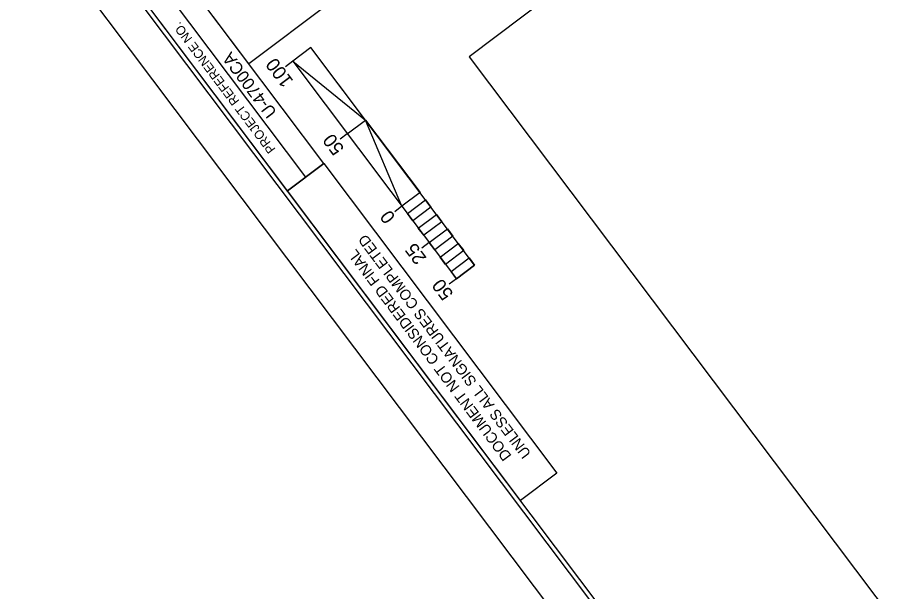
# Model space of a CAD drawing. Extents: x 1262861 to 1264804, y 775326 to 777329.
# Drawn here: x 1262916.5 to 1263399.5, y 776290.5 to 776605.9 of the extents above; entities that cross this region are included whole.
import ezdxf

# ---------------------------------------------------------------- set-up
doc = ezdxf.new("R2010")
doc.units = 0
for name, color, linetype in [('Sheet Data Field CELL', 7, 'Continuous'), ('Sheet Plan CELL', 7, 'Continuous'), ('Sheet Plot Border Inside CELL', 7, 'Continuous'), ('Sheet Plot Border Outside CELL', 7, 'Continuous'), ('Sheet Sticker Exception Certification CELL', 7, 'Continuous'), ('Sheet Title CELL', 7, 'Continuous'), ('Sheet Typical CELL', 7, 'Continuous')]:
    doc.layers.add(name, color=color, linetype=linetype)

msp = doc.modelspace()

# ---------------------------------------------------------------- linework, layer by layer
at = {"layer": 'Sheet Data Field CELL'}
for p, q in [((1263067.87, 776581.93), (1263063.88, 776578.92)), ((1263097.9, 776542.05), (1263093.92, 776539.06)), ((1263142.96, 776482.25), (1263138.97, 776479.24)), ((1263157.97, 776462.3), (1263153.99, 776459.3))]:
    msp.add_line(p, q, dxfattribs=at)
at = {"layer": 'Sheet Plan CELL'}
msp.add_lwpolyline([(1263054.56, 776753.11), (1263133.61, 776648.16), (1263043.77, 776580.5), (1262964.72, 776685.44)], dxfattribs=at)
msp.add_lwpolyline([(1263054.56, 776753.11), (1263133.61, 776648.16), (1263043.77, 776580.5), (1262964.72, 776685.44)], dxfattribs=at)
at = {"layer": 'Sheet Plot Border Inside CELL'}
msp.add_lwpolyline([(1264780.22, 775982.89), (1263777.88, 777313.61), (1262935.19, 776678.9), (1263937.52, 775348.16)], close=True, dxfattribs=at)
at = {"layer": 'Sheet Plot Border Outside CELL'}
msp.add_lwpolyline([(1262916.5, 776670.46), (1263929.36, 775325.74), (1264804.01, 775984.53), (1263791.15, 777329.26)], close=True, dxfattribs=at)
at = {"layer": 'Sheet Sticker Exception Certification CELL'}
for p, q in [((1263065.04, 776510.63), (1263085.04, 776525.69)), ((1263085.03, 776525.68), (1263213.21, 776355.5)), ((1263193.22, 776340.44), (1263065.03, 776510.62)), ((1263213.21, 776355.5), (1263193.22, 776340.44))]:
    msp.add_line(p, q, dxfattribs=at)
at = {"layer": 'Sheet Title CELL'}
for p, q in [((1263077.86, 776589.44), (1263067.88, 776581.93)), ((1263167.95, 776469.81), (1263077.86, 776589.44)), ((1263067.88, 776581.93), (1263063.89, 776578.92)), ((1263067.88, 776581.93), (1263157.99, 776462.3)), ((1263097.92, 776542.05), (1263107.88, 776549.56)), ((1263097.92, 776542.05), (1263093.94, 776539.05)), ((1263127.96, 776502.18), (1263123.97, 776499.18)), ((1263136.96, 776490.21), (1263146.93, 776497.72)), ((1263142.98, 776482.24), (1263138.98, 776479.23)), ((1263157.99, 776462.3), (1263167.95, 776469.81)), ((1263157.99, 776462.3), (1263154.01, 776459.3)), ((1263154.01, 776459.3), (1263154.01, 776459.3)), ((1263157.99, 776462.3), (1263157.99, 776462.3))]:
    msp.add_line(p, q, dxfattribs=at)
for points in [[(1263067.88, 776581.93), (1263107.88, 776549.56), (1263077.81, 776589.5)], [(1263127.96, 776502.18), (1263107.88, 776549.56), (1263137.93, 776509.69)], [(1263133.96, 776494.2), (1263130.95, 776498.19), (1263140.93, 776505.7), (1263143.93, 776501.71)], [(1263139.97, 776486.23), (1263136.96, 776490.21), (1263146.93, 776497.72), (1263149.93, 776493.73)], [(1263145.98, 776478.26), (1263142.98, 776482.24), (1263152.94, 776489.74), (1263155.94, 776485.76)], [(1263151.98, 776470.27), (1263148.98, 776474.27), (1263158.95, 776481.78), (1263161.95, 776477.8)], [(1263157.99, 776462.3), (1263154.98, 776466.29), (1263164.95, 776473.79), (1263167.95, 776469.81)]]:
    msp.add_lwpolyline(points, close=True, dxfattribs=at)
at = {"layer": 'Sheet Typical CELL'}
for p, q in [((1263085.07, 776525.72), (1262964.72, 776685.5)), ((1263075.06, 776518.17), (1262954.71, 776677.96)), ((1263065.04, 776510.63), (1262944.69, 776670.41)), ((1263847.15, 775472.26), (1262944.69, 776670.41)), ((1263085.07, 776525.72), (1263065.04, 776510.63))]:
    msp.add_line(p, q, dxfattribs=at)
msp.add_lwpolyline([(1263818.15, 776448.22), (1263516.3, 776848.97), (1263165.03, 776584.39), (1263466.88, 776183.64)], close=True, dxfattribs=at)

# ---------------------------------------------------------------- texts
at = {"layer": 'Sheet Data Field CELL'}
for s, height, p in [('U-4700CA', 6.748, (1263059.42, 776553.89)), ('100', 7.488, (1263068.5, 776571.12)), ('50', 7.488, (1263096.55, 776533.9)), ('25', 7.488, (1263141.81, 776473.82)), ('50', 7.488, (1263156.62, 776454.15))]:
    msp.add_text(s, height=height, rotation=126.9874, dxfattribs=at).set_placement(p)
at = {"layer": 'Sheet Plan CELL'}
msp.add_text('PROJECT REFERENCE NO.', height=5.0001, rotation=126.9874, dxfattribs=at).set_placement((1263058.65, 776533.6))
at = {"layer": 'Sheet Sticker Exception Certification CELL'}
for s, p in [('UNLESS ALL SIGNATURES COMPLETED', (1263199.25, 776366.32)), ('DOCUMENT NOT CONSIDERED FINAL', (1263188.51, 776365))]:
    msp.add_text(s, height=5.8579, rotation=126.9874, dxfattribs=at).set_placement(p)
at = {"layer": 'Sheet Title CELL'}
msp.add_text('0', height=7.49, rotation=126.9874, dxfattribs=at).set_placement((1263124.71, 776496.29))

doc.saveas('drawing.dxf')
